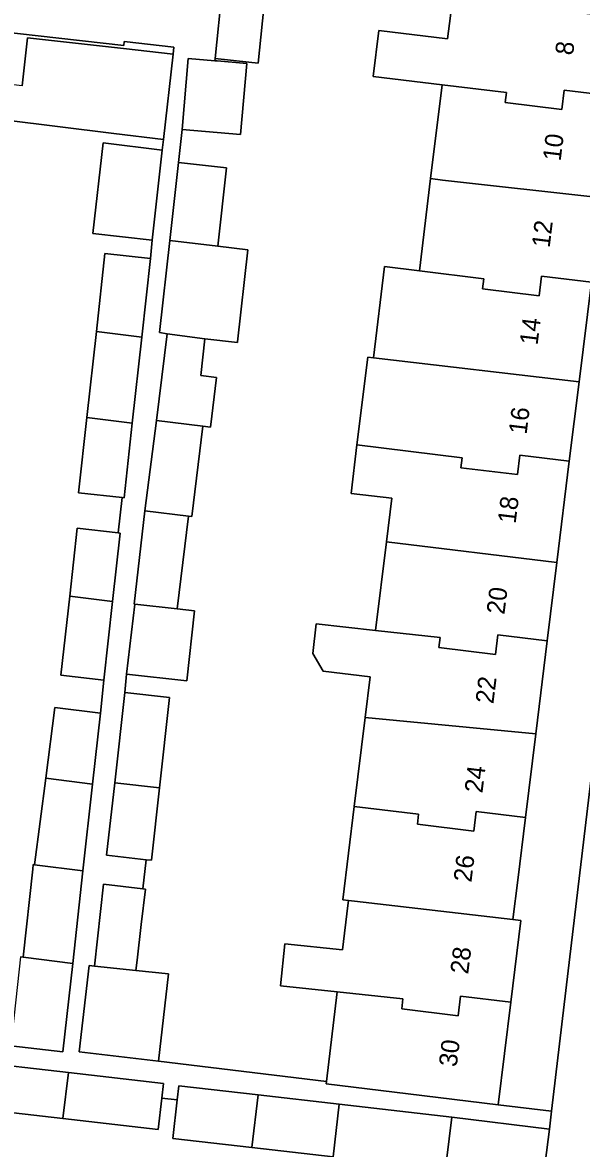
# Model space of a CAD drawing. Extents: x 158086 to 159499, y 382904 to 383981.
# Drawn here: x 158278.9 to 158309.8, y 383302.1 to 383364.2 of the extents above; entities that cross this region are included whole.
import ezdxf

# ---------------------------------------------------------------- set-up
doc = ezdxf.new("R2010")
doc.units = 0
for name, color, linetype in [('IMGEO_Erf', 7, 'Continuous'), ('IMGEO_Pand', 7, 'Continuous'), ('IMGEO_Pand_nummerreeks', 7, 'Continuous'), ('IMGEO_Voetpad_open', 7, 'Continuous')]:
    doc.layers.add(name, color=color, linetype=linetype)

msp = doc.modelspace()

# ---------------------------------------------------------------- linework, layer by layer
at = {"layer": 'IMGEO_Erf'}
for points in [[(158312.566, 383364.413), (158312.516, 383364.007), (158312.079, 383364.061), (158311.6, 383360.171), (158310.909, 383354.558), (158310.335, 383349.894), (158309.659, 383344.401), (158309.119, 383340.015), (158308.43, 383334.426), (158307.897, 383330.09), (158307.266, 383324.969), (158306.696, 383320.335), (158306.271, 383316.881), (158306.003, 383314.709), (158306.44, 383314.658), (158305.882, 383310.137), (158305.185, 383304.485), (158308.137, 383304.132), (158309.154, 383312.647), (158312.006, 383336.596), (158317.256, 383379.22)], [(158292.321, 383365.788), (158291.945, 383361.983), (158291.426, 383362.042), (158289.56, 383362.256), (158289.545, 383362.127), (158289.672, 383362.116), (158291.314, 383361.972), (158290.97, 383358.05), (158287.736, 383358.334), (158287.535, 383356.514), (158290.187, 383356.219), (158289.705, 383351.883), (158291.371, 383351.679), (158290.808, 383346.608), (158290.804, 383346.572), (158288.998, 383346.772), (158288.772, 383344.739), (158289.646, 383344.633), (158289.313, 383341.903), (158288.886, 383341.955), (158288.277, 383336.962), (158288.099, 383336.984), (158287.475, 383331.865), (158288.426, 383331.76), (158287.997, 383327.888), (158284.671, 383328.256), (158284.571, 383327.25), (158287.052, 383326.975), (158286.499, 383321.982), (158286.055, 383317.979), (158285.753, 383318.012), (158285.575, 383316.402), (158285.713, 383316.386), (158285.486, 383314.425), (158285.26, 383312.464), (158285.194, 383311.895), (158286.984, 383311.705), (158286.43, 383306.897), (158295.707, 383305.768), (158296.309, 383310.716), (158293.164, 383311.05), (158293.41, 383313.368), (158296.59, 383313.031), (158296.889, 383315.485), (158296.923, 383315.768), (158296.617, 383315.802), (158297.244, 383320.958), (158297.842, 383325.866), (158298.115, 383328.113), (158295.527, 383328.428), (158294.961, 383329.403), (158295.138, 383331.028), (158298.426, 383330.669), (158299.022, 383335.571), (158299.313, 383337.965), (158297.067, 383338.24), (158297.394, 383340.915), (158297.987, 383345.768), (158298.309, 383345.73), (158298.922, 383350.757), (158300.842, 383350.522), (158301.463, 383355.629), (158302.092, 383360.801), (158298.298, 383361.265), (158298.607, 383363.791), (158302.399, 383363.33), (158302.504, 383364.19), (158302.665, 383365.511)], [(158278.913, 383360.738), (158279.211, 383363.388), (158284.506, 383362.793), (158287.238, 383362.486), (158287.282, 383362.881), (158284.55, 383363.188), (158284.525, 383362.963), (158273.9, 383364.156)], [(158278.824, 383312.648), (158278.957, 383312.631), (158279.493, 383317.488), (158279.521, 383317.739), (158279.598, 383317.729), (158280.212, 383322.505), (158280.715, 383326.421), (158283.226, 383326.11), (158283.425, 383327.93), (158281.054, 383328.192), (158281.536, 383332.557), (158281.951, 383336.31), (158284.219, 383336.059), (158284.435, 383338.007), (158282.025, 383338.273), (158282.483, 383342.426), (158283.007, 383347.171), (158283.482, 383351.476), (158285.994, 383351.198), (158286.087, 383352.228), (158282.817, 383352.595), (158283.379, 383357.6), (158286.644, 383357.193), (158286.709, 383357.771), (158283.98, 383358.111), (158277.901, 383358.868)], [(158274.859, 383297.735), (158280.335, 383297.062), (158285.626, 383296.411), (158290.813, 383295.773), (158296.331, 383295.094), (158296.327, 383294.69), (158301.418, 383294.067), (158302.131, 383299.898), (158304.922, 383299.556), (158304.209, 383293.725), (158306.922, 383293.393), (158307.539, 383299.409), (158302.179, 383300.065), (158302.637, 383303.8), (158296.414, 383304.508), (158296.08, 383301.598), (158291.589, 383302.113), (158287.225, 383302.613), (158287.47, 383304.749), (158286.625, 383304.846), (158286.426, 383303.113), (158281.15, 383303.718), (158275.691, 383304.344)]]:
    msp.add_lwpolyline(points, dxfattribs=at)
at = {"layer": 'IMGEO_Pand'}
for points in [[(158289.954, 383366.064), (158289.56, 383362.256), (158291.426, 383362.042), (158291.945, 383361.983), (158292.321, 383365.788)], [(158312.566, 383364.413), (158303.13, 383365.561), (158303.117, 383365.456), (158302.665, 383365.511), (158302.504, 383364.19), (158302.399, 383363.33), (158298.607, 383363.791), (158298.298, 383361.265), (158302.092, 383360.801), (158305.65, 383360.366), (158305.583, 383359.814), (158308.703, 383359.433), (158308.834, 383360.509), (158311.6, 383360.171), (158312.079, 383364.061), (158312.516, 383364.007)], [(158287.238, 383362.486), (158284.506, 383362.793), (158279.211, 383363.388), (158278.913, 383360.738), (158278.121, 383360.827), (158277.901, 383358.868), (158283.98, 383358.111), (158286.709, 383357.771)], [(158289.672, 383362.116), (158289.545, 383362.127), (158288.08, 383362.256), (158287.736, 383358.334), (158290.97, 383358.05), (158291.314, 383361.972)], [(158310.909, 383354.558), (158311.6, 383360.171), (158308.834, 383360.509), (158308.703, 383359.433), (158305.583, 383359.814), (158305.65, 383360.366), (158302.092, 383360.801), (158301.463, 383355.629), (158302.125, 383355.532)], [(158286.644, 383357.193), (158283.379, 383357.6), (158282.817, 383352.595), (158286.087, 383352.228)], [(158290.187, 383356.219), (158287.535, 383356.514), (158287.057, 383352.207), (158289.705, 383351.883)], [(158310.909, 383354.558), (158302.125, 383355.532), (158301.463, 383355.629), (158300.842, 383350.522), (158304.399, 383350.087), (158304.332, 383349.535), (158307.452, 383349.154), (158307.583, 383350.23), (158310.335, 383349.894)], [(158291.371, 383351.679), (158289.705, 383351.883), (158287.057, 383352.207), (158286.492, 383347.113), (158286.918, 383347.055), (158288.998, 383346.772), (158290.804, 383346.572), (158290.808, 383346.608)], [(158285.994, 383351.198), (158283.482, 383351.476), (158283.007, 383347.171), (158285.515, 383346.861)], [(158310.335, 383349.894), (158307.583, 383350.23), (158307.452, 383349.154), (158304.332, 383349.535), (158304.399, 383350.087), (158300.842, 383350.522), (158298.922, 383350.757), (158298.309, 383345.73), (158309.659, 383344.401)], [(158285.515, 383346.861), (158283.007, 383347.171), (158282.483, 383342.426), (158284.992, 383342.121)], [(158288.998, 383346.772), (158286.918, 383347.055), (158286.334, 383342.266), (158288.886, 383341.955), (158289.313, 383341.903), (158289.646, 383344.633), (158288.772, 383344.739)], [(158309.659, 383344.401), (158298.309, 383345.73), (158297.987, 383345.768), (158297.394, 383340.915), (158303.196, 383340.206), (158303.129, 383339.654), (158306.249, 383339.273), (158306.38, 383340.349), (158309.119, 383340.015)], [(158284.992, 383342.121), (158282.483, 383342.426), (158282.025, 383338.273), (158284.435, 383338.007), (158284.537, 383337.996)], [(158288.886, 383341.955), (158286.334, 383342.266), (158285.689, 383337.278), (158288.099, 383336.984), (158288.277, 383336.962)], [(158297.394, 383340.915), (158297.067, 383338.24), (158299.313, 383337.965), (158299.022, 383335.571), (158308.43, 383334.426), (158309.119, 383340.015), (158306.38, 383340.349), (158306.249, 383339.273), (158303.129, 383339.654), (158303.196, 383340.206)], [(158288.099, 383336.984), (158285.689, 383337.278), (158285.089, 383332.126), (158285.125, 383332.122), (158287.475, 383331.865)], [(158284.219, 383336.059), (158281.951, 383336.31), (158281.536, 383332.557), (158283.904, 383332.261), (158284.322, 383336.048)], [(158308.43, 383334.426), (158299.022, 383335.571), (158298.426, 383330.669), (158301.988, 383330.28), (158301.921, 383329.728), (158305.041, 383329.347), (158305.172, 383330.423), (158307.897, 383330.09)], [(158283.904, 383332.261), (158281.536, 383332.557), (158281.054, 383328.192), (158283.425, 383327.93)], [(158288.426, 383331.76), (158287.475, 383331.865), (158285.125, 383332.122), (158284.671, 383328.256), (158287.997, 383327.888)], [(158307.897, 383330.09), (158305.172, 383330.423), (158305.041, 383329.347), (158301.921, 383329.728), (158301.988, 383330.28), (158298.426, 383330.669), (158295.138, 383331.028), (158294.961, 383329.403), (158295.527, 383328.428), (158298.115, 383328.113), (158297.842, 383325.866), (158307.266, 383324.969)], [(158284.571, 383327.25), (158284.018, 383322.257), (158286.499, 383321.982), (158287.052, 383326.975)], [(158283.226, 383326.11), (158280.715, 383326.421), (158280.212, 383322.505), (158282.793, 383322.186)], [(158307.266, 383324.969), (158297.842, 383325.866), (158297.244, 383320.958), (158300.8, 383320.523), (158300.733, 383319.971), (158303.853, 383319.59), (158303.984, 383320.666), (158306.696, 383320.335)], [(158282.793, 383322.186), (158280.212, 383322.505), (158279.598, 383317.729), (158282.265, 383317.4)], [(158286.499, 383321.982), (158284.018, 383322.257), (158283.574, 383318.254), (158285.753, 383318.012), (158286.055, 383317.979)], [(158306.696, 383320.335), (158303.984, 383320.666), (158303.853, 383319.59), (158300.733, 383319.971), (158300.8, 383320.523), (158297.244, 383320.958), (158296.617, 383315.802), (158296.923, 383315.768), (158297.257, 383315.731), (158306.003, 383314.709), (158306.271, 383316.881)], [(158282.265, 383317.4), (158279.598, 383317.729), (158279.521, 383317.739), (158279.493, 383317.488), (158278.957, 383312.631), (158281.699, 383312.277)], [(158285.575, 383316.402), (158283.396, 383316.653), (158282.895, 383312.139), (158285.194, 383311.895), (158285.26, 383312.464), (158285.486, 383314.425), (158285.713, 383316.386)], [(158306.003, 383314.709), (158297.257, 383315.731), (158296.923, 383315.768), (158296.889, 383315.485), (158296.59, 383313.031), (158293.41, 383313.368), (158293.164, 383311.05), (158296.309, 383310.716), (158299.936, 383310.331), (158299.869, 383309.779), (158302.989, 383309.398), (158303.12, 383310.474), (158305.882, 383310.137), (158306.44, 383314.658)], [(158281.699, 383312.277), (158278.957, 383312.631), (158278.824, 383312.648), (158278.282, 383307.728), (158281.162, 383307.41)], [(158286.984, 383311.705), (158285.194, 383311.895), (158282.895, 383312.139), (158282.602, 383312.17), (158282.052, 383307.402), (158286.43, 383306.897)], [(158305.882, 383310.137), (158303.12, 383310.474), (158302.989, 383309.398), (158299.869, 383309.779), (158299.936, 383310.331), (158296.309, 383310.716), (158295.707, 383305.768), (158295.691, 383305.64), (158300.222, 383305.089), (158305.185, 383304.485)], [(158281.461, 383306.262), (158275.983, 383306.89), (158275.691, 383304.344), (158281.15, 383303.718)], [(158286.625, 383304.846), (158286.718, 383305.659), (158281.461, 383306.262), (158281.15, 383303.718), (158286.426, 383303.113)], [(158291.945, 383305.02), (158287.559, 383305.523), (158287.47, 383304.749), (158287.225, 383302.613), (158291.589, 383302.113)], [(158291.945, 383305.02), (158291.589, 383302.113), (158296.08, 383301.598), (158296.414, 383304.508)], [(158308.019, 383303.141), (158302.637, 383303.8), (158302.179, 383300.065), (158307.539, 383299.409)]]:
    msp.add_lwpolyline(points, close=True, dxfattribs=at)
at = {"layer": 'IMGEO_Voetpad_open'}
for points in [[(158301.714, 383410.302), (158299.049, 383412.9), (158298.48, 383413.344), (158296.89, 383412.261), (158301.675, 383405.273), (158309.562, 383393.621), (158311.105, 383391.342), (158311.12, 383391.319), (158317.588, 383381.778), (158317.256, 383379.22), (158312.006, 383336.596), (158309.154, 383312.647), (158308.137, 383304.132), (158308.019, 383303.141), (158307.539, 383299.409), (158306.922, 383293.393), (158305.835, 383284.427), (158305.519, 383281.801), (158305.419, 383281.454), (158308.472, 383280.426), (158308.504, 383280.698)], [(158275.983, 383306.89), (158281.461, 383306.262), (158286.718, 383305.659), (158286.625, 383304.846), (158287.47, 383304.749), (158287.559, 383305.523), (158291.945, 383305.02), (158296.414, 383304.508), (158302.637, 383303.8), (158308.019, 383303.141), (158308.137, 383304.132), (158305.185, 383304.485), (158300.222, 383305.089), (158295.691, 383305.64), (158295.707, 383305.768), (158286.43, 383306.897), (158282.052, 383307.402), (158282.602, 383312.17), (158282.895, 383312.139), (158283.396, 383316.653), (158285.575, 383316.402), (158285.753, 383318.012), (158283.574, 383318.254), (158284.018, 383322.257), (158284.571, 383327.25), (158284.671, 383328.256), (158285.125, 383332.122), (158285.089, 383332.126), (158285.689, 383337.278), (158286.334, 383342.266), (158286.918, 383347.055), (158286.492, 383347.113), (158287.057, 383352.207), (158287.535, 383356.514), (158287.736, 383358.334), (158288.08, 383362.256), (158289.545, 383362.127), (158289.56, 383362.256), (158289.954, 383366.064)], [(158273.9, 383364.156), (158284.525, 383362.963), (158284.55, 383363.188), (158287.282, 383362.881), (158287.238, 383362.486), (158286.709, 383357.771), (158286.644, 383357.193), (158286.087, 383352.228), (158285.994, 383351.198), (158285.515, 383346.861), (158284.992, 383342.121), (158284.537, 383337.996), (158284.435, 383338.007), (158284.219, 383336.059), (158284.322, 383336.048), (158283.904, 383332.261), (158283.425, 383327.93), (158283.226, 383326.11), (158282.793, 383322.186), (158282.265, 383317.4), (158281.699, 383312.277), (158281.162, 383307.41), (158278.282, 383307.728)]]:
    msp.add_lwpolyline(points, dxfattribs=at)

# ---------------------------------------------------------------- texts
at = {"layer": 'IMGEO_Pand_nummerreeks'}
for s, rotation, p in [('8', 82.98148, (158309.32, 383362.397)), ('10', 82.98119, (158308.637, 383356.556)), ('12', 82.98148, (158308.03, 383351.772)), ('14', 82.98148, (158307.363, 383346.392)), ('16', 82.98148, (158306.757, 383341.464)), ('18', 82.98119, (158306.152, 383336.538)), ('20', 82.98119, (158305.534, 383331.521)), ('22', 82.98148, (158304.925, 383326.588)), ('24', 82.98119, (158304.32, 383321.662)), ('26', 82.98148, (158303.712, 383316.735)), ('28', 82.96429, (158303.532, 383311.66)), ('30', 82.96429, (158302.9, 383306.538))]:
    msp.add_text(s, height=1, rotation=rotation, dxfattribs=at).set_placement(p)

doc.saveas('drawing.dxf')
